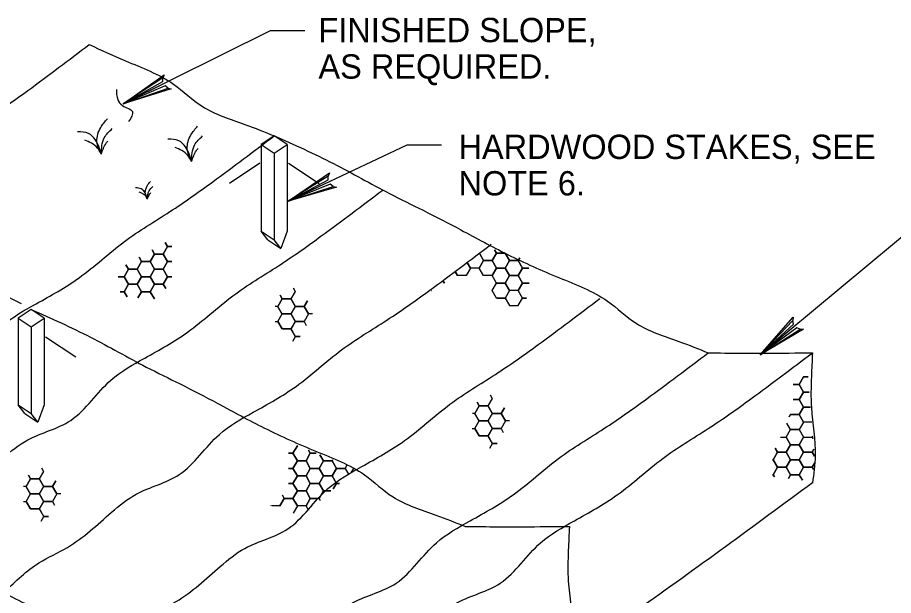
# Model space of a CAD drawing. Extents: x 3 to 3592, y -602 to 1171.
# Drawn here: x 412.5 to 538.6, y 841.3 to 924.6 of the extents above; entities that cross this region are included whole.
import ezdxf

# ---------------------------------------------------------------- set-up
doc = ezdxf.new("R2010")
doc.units = 0
doc.layers.add('2', color=7, linetype='Continuous')
doc.layers.add('3', color=7, linetype='Continuous')

msp = doc.modelspace()

# ---------------------------------------------------------------- linework, layer by layer
at = {"layer": '2'}
for p, q in [((449.46, 907.53), (449.46, 907.53)), ((449.46, 907.53), (449.46, 907.53)), ((449.46, 907.53), (449.46, 907.53)), ((449.46, 907.53), (449.46, 907.53)), ((449.46, 907.53), (449.46, 907.53)), ((449.46, 907.53), (449.46, 907.53)), ((447.58, 906.28), (447.58, 893.78)), ((451.33, 906.28), (451.33, 893.78)), ((451.33, 906.28), (451.33, 906.28)), ((449.46, 905.03), (449.46, 892.53)), ((447.39, 903.59), (443.01, 900.68)), ((451.33, 903.59), (451.33, 903.59)), ((451.53, 903.59), (455.9, 900.68)), ((457.27, 903.63), (457.27, 903.63)), ((447.58, 893.78), (449.46, 892.53)), ((448.52, 892.53), (447.58, 893.78)), ((451.33, 893.78), (450.39, 891.28)), ((448.52, 892.53), (450.39, 891.28)), ((450.39, 891.28), (449.46, 892.53)), ((480.71, 891.91), (480.71, 891.91)), ((413.05, 883.31), (404.04, 887.82)), ((496.33, 884.09), (496.33, 884.09)), ((414.46, 882.53), (414.46, 882.53)), ((414.46, 882.53), (414.46, 882.53)), ((414.46, 882.53), (414.46, 882.53)), ((414.46, 882.53), (414.46, 882.53)), ((414.46, 882.53), (414.46, 882.53)), ((414.46, 882.53), (414.46, 882.53)), ((412.58, 881.28), (412.58, 868.78)), ((416.33, 881.28), (416.33, 868.78)), ((416.33, 881.28), (416.33, 881.28)), ((414.46, 880.03), (414.46, 867.53)), ((416.33, 878.59), (416.33, 878.59)), ((416.53, 878.59), (420.9, 875.68)), ((422.27, 878.63), (422.27, 878.63)), ((511.96, 876.28), (511.96, 876.28)), ((412.58, 868.78), (414.46, 867.53)), ((413.52, 867.53), (412.58, 868.78)), ((416.33, 868.78), (415.39, 866.28)), ((413.52, 867.53), (415.39, 866.28)), ((415.39, 866.28), (414.46, 867.53))]:
    msp.add_line(p, q, dxfattribs=at)
for points in [[(453.87, 922.65), (448.87, 922.65), (427.7, 912.12)], [(434.18, 914.39), (433.73, 914.72), (427.7, 912.12), (434.18, 914.39), (434.62, 914.28), (427.7, 912.12), (433.42, 915.33), (433.42, 915.87), (427.7, 912.12), (433.6, 916.33), (433.42, 915.87)], [(473.56, 906.19), (468.56, 906.19), (451.44, 898.1)], [(457.96, 900.23), (457.52, 900.57), (451.44, 898.1), (457.96, 900.23), (458.4, 900.11), (451.44, 898.1), (457.22, 901.19), (457.23, 901.73), (451.44, 898.1), (457.42, 902.18), (457.23, 901.73)], [(547.75, 895.4), (542.75, 895.4), (519.42, 875.97)], [(433.76, 892.15), (434.09, 891.57)], [(434.09, 891.57), (433.76, 892.15)], [(431.87, 891.09), (432.22, 890.49)], [(432.22, 890.49), (431.87, 891.09)], [(434.09, 891.57), (433.47, 890.49)], [(433.47, 890.49), (434.09, 891.57), (434.7, 891.57)], [(434.7, 891.57), (434.09, 891.57)], [(481.45, 890.65), (480.83, 889.57)], [(480.83, 889.57), (481.45, 890.65)], [(481.19, 891.1), (481.45, 890.65)], [(481.45, 890.65), (481.19, 891.1)], [(481.45, 890.65), (482.61, 890.65)], [(482.61, 890.65), (481.45, 890.65)], [(482.72, 890.62), (483.33, 889.57)], [(483.33, 889.57), (482.72, 890.62)], [(430.34, 889.41), (429.72, 888.33)], [(430.34, 889.41), (429.99, 890.03)], [(429.99, 890.03), (430.34, 889.41)], [(431.59, 889.41), (430.34, 889.41)], [(432.22, 890.49), (431.59, 889.41)], [(433.47, 890.49), (432.22, 890.49)], [(434.7, 889.41), (434.09, 889.41), (433.47, 890.49)], [(433.47, 888.33), (434.09, 889.41), (434.7, 889.41)], [(479.58, 889.57), (478.95, 888.49)], [(479.04, 890.51), (479.58, 889.57)], [(479.58, 889.57), (479.04, 890.51)], [(480.83, 889.57), (479.58, 889.57)], [(481.45, 888.49), (480.83, 889.57)], [(483.33, 889.57), (482.7, 888.49)], [(484.58, 889.57), (483.33, 889.57)], [(484.8, 889.97), (484.58, 889.57)], [(484.58, 889.57), (484.8, 889.97)], [(485.2, 888.49), (484.58, 889.57)], [(428.47, 888.33), (427.84, 887.24)], [(428.47, 888.33), (428.1, 888.96)], [(428.1, 888.96), (428.47, 888.33)], [(429.72, 888.33), (428.47, 888.33)], [(434.7, 887.24), (434.09, 887.24), (433.47, 888.33)], [(477.7, 888.49), (477.08, 887.41)], [(477.7, 888.49), (477.29, 889.2)], [(477.29, 889.2), (477.7, 888.49)], [(478.95, 888.49), (477.7, 888.49)], [(482.7, 888.49), (481.45, 888.49)], [(484.58, 887.41), (485.2, 888.49)], [(485.2, 888.49), (486.12, 888.49)], [(486.12, 888.49), (485.2, 888.49)], [(427.84, 887.24), (426.96, 887.24)], [(426.96, 887.24), (427.84, 887.24)], [(427.84, 887.24), (428.47, 886.16)], [(433.47, 886.16), (434.09, 887.24), (434.7, 887.24)], [(475.83, 887.41), (475.55, 887.89)], [(475.55, 887.89), (475.83, 887.41)], [(477.08, 887.41), (475.83, 887.41)], [(485.2, 886.32), (484.58, 887.41)], [(428.47, 886.16), (427.84, 885.08)], [(427.84, 885.08), (428.47, 886.16)], [(428.47, 886.16), (429.72, 886.16)], [(429.72, 886.16), (430.34, 885.08)], [(431.59, 885.08), (432.22, 886.16)], [(432.22, 886.16), (433.47, 886.16)], [(433.83, 885.53), (433.47, 886.16)], [(433.47, 886.16), (433.83, 885.53)], [(452.19, 885.64), (452.48, 885.13)], [(473.95, 886.32), (473.8, 886.58)], [(473.8, 886.58), (473.95, 886.32)], [(484.58, 885.24), (485.2, 886.32)], [(485.2, 886.32), (486.14, 886.32)], [(486.14, 886.32), (485.2, 886.32)], [(427.84, 885.08), (427.26, 885.08)], [(427.26, 885.08), (427.84, 885.08)], [(428.28, 884.32), (427.84, 885.08)], [(427.84, 885.08), (428.28, 884.32)], [(430.34, 885.08), (429.83, 884.19)], [(429.83, 884.19), (430.34, 885.08)], [(430.34, 885.08), (431.59, 885.08)], [(432.2, 884.03), (431.59, 885.08)], [(431.59, 885.08), (432.2, 884.03)], [(450.31, 884.56), (450.61, 884.04)], [(450.61, 884.04), (450.31, 884.56)], [(452.48, 885.13), (451.86, 884.04)], [(451.88, 884.03), (452.16, 884.52)], [(472.08, 885.24), (472.06, 885.27)], [(472.06, 885.27), (472.08, 885.24)], [(485.2, 884.16), (484.58, 885.24)], [(450.61, 884.04), (449.98, 882.96)], [(451.86, 884.04), (450.61, 884.04)], [(452.5, 882.95), (451.88, 884.03)], [(454.22, 883.77), (453.75, 882.95)], [(453.75, 882.95), (454.22, 883.77)], [(481.45, 884.16), (482.7, 884.16)], [(482.7, 884.16), (483.33, 883.08)], [(483.33, 883.08), (484.58, 883.08)], [(484.58, 883.08), (485.2, 884.16)], [(484.58, 883.08), (484.61, 883.02)], [(484.61, 883.02), (484.58, 883.08)], [(485.2, 884.16), (485.77, 884.16)], [(485.77, 884.16), (485.2, 884.16)], [(449.98, 882.96), (449.61, 882.96)], [(449.98, 880.8), (450.61, 881.88)], [(450.61, 881.88), (451.86, 881.88)], [(451.86, 881.88), (452.48, 880.8)], [(451.88, 881.87), (452.5, 882.95)], [(452.5, 880.78), (451.88, 881.87)], [(453.75, 882.95), (452.5, 882.95)], [(452.5, 882.95), (453.75, 882.95)], [(454.38, 881.87), (453.75, 882.95)], [(453.75, 882.95), (454.38, 881.87)], [(454.38, 881.87), (453.75, 880.78)], [(454.95, 881.87), (454.38, 881.87)], [(449.58, 880.8), (449.98, 880.8)], [(449.98, 880.8), (450.61, 879.72)], [(450.61, 879.72), (449.98, 880.8)], [(452.48, 880.8), (451.86, 879.71)], [(451.88, 879.7), (452.5, 880.78)], [(452.5, 880.78), (453.75, 880.78)], [(453.75, 880.78), (452.5, 880.78)], [(453.75, 880.78), (454.07, 880.23)], [(525.2, 879.68), (524.69, 879.89), (519.42, 875.97), (525.2, 879.68), (525.66, 879.67), (519.42, 875.97), (524.25, 880.42), (524.12, 880.94), (519.42, 875.97), (524.2, 881.43), (524.12, 880.94)], [(450.62, 879.71), (451.86, 879.71)], [(451.86, 879.71), (450.62, 879.71)], [(451.86, 879.71), (452.14, 879.23)], [(452.5, 878.62), (451.88, 879.7)], [(452.11, 877.95), (452.5, 878.62)], [(453.2, 878.62), (452.5, 878.62)], [(452.5, 878.62), (453.2, 878.62)], [(525.05, 871.71), (524.18, 871.71)], [(524.18, 871.71), (525.05, 871.71)], [(525.68, 872.8), (525.05, 871.71)], [(525.05, 871.71), (525.68, 872.8)], [(525.68, 870.63), (525.05, 871.71)], [(525.05, 871.71), (525.68, 870.63)], [(525.62, 872.89), (525.68, 872.8)], [(525.68, 872.8), (525.62, 872.89)], [(525.68, 872.8), (526.32, 872.8)], [(526.32, 872.8), (525.68, 872.8)], [(525.68, 870.63), (525.05, 869.55)], [(525.05, 869.55), (525.68, 870.63)], [(526.5, 870.63), (525.68, 870.63)], [(525.68, 870.63), (526.5, 870.63)], [(478.67, 869.16), (478.97, 868.64)], [(478.97, 868.64), (478.67, 869.16)], [(480.85, 869.72), (480.22, 868.64)], [(480.24, 868.62), (480.53, 869.12)], [(480.55, 870.23), (480.85, 869.72)], [(524.18, 869.55), (525.05, 869.55), (525.68, 868.47), (525.05, 867.38), (523.8, 867.38), (523.77, 867.44)], [(525.05, 869.55), (524.18, 869.55)], [(525.68, 868.47), (525.05, 869.55)], [(478.97, 868.64), (478.35, 867.55)], [(480.22, 868.64), (478.97, 868.64)], [(480.87, 867.54), (480.24, 868.62)], [(482.59, 868.36), (482.12, 867.54)], [(482.12, 867.54), (482.59, 868.36)], [(525.05, 867.38), (525.68, 868.47)], [(526.68, 868.47), (525.68, 868.47)], [(525.68, 868.47), (526.68, 868.47)], [(478.35, 867.55), (477.98, 867.55)], [(480.24, 866.46), (480.87, 867.54)], [(482.12, 867.54), (480.87, 867.54)], [(480.87, 867.54), (482.12, 867.54)], [(482.74, 866.46), (482.12, 867.54)], [(482.12, 867.54), (482.74, 866.46)], [(523.61, 867.04), (523.8, 867.38), (525.05, 867.38), (525.68, 866.3), (525.05, 865.22), (523.8, 865.22), (523.26, 866.17)], [(523.77, 867.44), (523.8, 867.38), (523.61, 867.04)], [(525.68, 866.3), (525.05, 867.38)], [(477.94, 865.39), (478.35, 865.39)], [(478.35, 865.39), (478.97, 866.47)], [(478.35, 865.39), (478.97, 864.31)], [(478.97, 864.31), (478.35, 865.39)], [(478.97, 866.47), (480.22, 866.47)], [(480.22, 866.47), (480.85, 865.39)], [(480.85, 865.39), (480.22, 864.31)], [(480.87, 865.37), (480.24, 866.46)], [(480.24, 864.29), (480.87, 865.37)], [(480.87, 865.37), (482.12, 865.37)], [(482.12, 865.37), (480.87, 865.37)], [(482.74, 866.46), (482.12, 865.37)], [(482.12, 865.37), (482.43, 864.82)], [(483.32, 866.46), (482.74, 866.46)], [(526.86, 866.3), (525.68, 866.3)], [(478.98, 864.31), (480.22, 864.31)], [(480.22, 864.31), (478.98, 864.31)], [(480.22, 864.31), (480.5, 863.82)], [(480.87, 863.21), (480.24, 864.29)], [(522.36, 864.14), (523.18, 864.14), (523.8, 863.05), (523.18, 861.97), (521.93, 861.97), (521.58, 862.57)], [(525.05, 863.05), (525.68, 864.14)], [(525.68, 864.14), (526.93, 864.14)], [(526.93, 864.14), (527.02, 864.3)], [(526.93, 864.14), (527.05, 863.92)], [(527.05, 863.92), (526.93, 864.14)], [(452.78, 862.89), (452.15, 861.81)], [(452.15, 861.81), (452.78, 862.89)], [(452.76, 862.92), (452.78, 862.89)], [(452.78, 862.89), (452.83, 862.89)], [(480.48, 862.54), (480.87, 863.21)], [(481.56, 863.21), (480.87, 863.21)], [(480.87, 863.21), (481.56, 863.21)], [(525.68, 861.97), (525.05, 863.05)], [(451.51, 861.81), (452.15, 861.81), (452.78, 860.72), (452.15, 859.64), (451.51, 859.64)], [(452.15, 861.81), (451.51, 861.81)], [(452.78, 860.72), (452.15, 861.81)], [(454.65, 861.81), (454.03, 860.72)], [(454.03, 860.72), (454.65, 861.81)], [(454.39, 862.26), (454.65, 861.81)], [(454.65, 861.81), (454.39, 862.26)], [(454.65, 861.81), (455.51, 861.81)], [(455.51, 861.81), (454.65, 861.81)], [(456.02, 861.6), (456.53, 860.72)], [(456.53, 860.72), (456.02, 861.6)], [(521.58, 862.57), (521.93, 861.97), (521.3, 860.89), (521.2, 860.89)], [(525.05, 860.89), (525.68, 861.97)], [(525.68, 861.97), (526.93, 861.97)], [(526.93, 861.97), (525.68, 861.97)], [(527.18, 862.4), (526.93, 861.97)], [(526.93, 861.97), (527.18, 862.4)], [(526.93, 861.97), (527.26, 861.4)], [(527.26, 861.4), (526.93, 861.97)], [(454.03, 860.72), (452.78, 860.72)], [(454.65, 859.64), (454.03, 860.72)], [(456.53, 860.72), (455.9, 859.64)], [(455.9, 859.64), (456.53, 860.72)], [(456.53, 860.72), (457.78, 860.72)], [(457.78, 860.72), (456.53, 860.72)], [(457.85, 860.86), (457.78, 860.72)], [(457.78, 860.72), (457.85, 860.86)], [(457.78, 860.72), (458.4, 859.64)], [(458.4, 859.64), (457.78, 860.72)], [(521.2, 860.89), (521.3, 860.89), (521.93, 859.81), (521.3, 858.72), (521.2, 858.72)], [(525.68, 859.81), (525.05, 860.89)], [(527.3, 860.45), (526.93, 859.81)], [(526.93, 859.81), (527.3, 860.45)], [(416.24, 859.21), (415.61, 858.13)], [(415.94, 859.72), (416.24, 859.21)], [(451.51, 859.64), (452.15, 859.64), (452.78, 858.56), (452.15, 857.48), (451.51, 857.48)], [(455.9, 859.64), (454.65, 859.64)], [(456.53, 858.56), (455.9, 859.64)], [(458.4, 859.64), (457.78, 858.56)], [(457.78, 858.56), (458.4, 859.64)], [(458.4, 859.64), (459.65, 859.64)], [(459.65, 859.64), (458.4, 859.64)], [(459.88, 860.04), (459.65, 859.64)], [(459.65, 859.64), (460.2, 858.69)], [(460.52, 858.98), (460.9, 859.63)], [(521.3, 858.72), (521.93, 859.81)], [(521.93, 859.81), (523.18, 859.81)], [(523.18, 859.81), (523.8, 858.72)], [(525.05, 858.72), (525.68, 859.81)], [(526.93, 859.81), (525.68, 859.81)], [(525.68, 859.81), (526.93, 859.81)], [(527.12, 859.47), (526.93, 859.81)], [(526.93, 859.81), (527.12, 859.47)], [(414.36, 858.13), (413.74, 857.05)], [(414.06, 858.65), (414.36, 858.13)], [(414.36, 858.13), (414.06, 858.65)], [(415.61, 858.13), (414.36, 858.13)], [(415.63, 858.12), (415.92, 858.61)], [(416.26, 857.03), (415.63, 858.12)], [(417.98, 857.85), (417.51, 857.03)], [(417.51, 857.03), (417.98, 857.85)], [(455.9, 857.48), (456.53, 858.56)], [(456.53, 858.56), (457.78, 858.56)], [(457.78, 858.56), (456.53, 858.56)], [(457.78, 858.56), (458.4, 857.48)], [(458.4, 857.48), (457.78, 858.56)], [(521.2, 858.72), (521.3, 858.72)], [(521.49, 858.41), (521.3, 858.72)], [(521.3, 858.72), (521.49, 858.41)], [(523.8, 858.72), (523.49, 858.17)], [(523.49, 858.17), (523.8, 858.72)], [(523.8, 858.72), (525.05, 858.72)], [(525.51, 857.93), (525.05, 858.72)], [(525.05, 858.72), (525.51, 857.93)], [(413.74, 857.05), (413.37, 857.05)], [(415.63, 855.95), (416.26, 857.03)], [(417.51, 857.03), (416.26, 857.03)], [(416.26, 857.03), (417.51, 857.03)], [(418.13, 855.95), (417.51, 857.03)], [(417.51, 857.03), (418.13, 855.95)], [(451.51, 857.48), (452.15, 857.48), (452.78, 856.39), (452.15, 855.31), (450.9, 855.31), (450.64, 855.76)], [(454.03, 856.39), (454.65, 857.48)], [(454.65, 857.48), (455.9, 857.48)], [(455.9, 857.48), (456.53, 856.39)], [(456.53, 856.39), (455.9, 857.48)], [(458.4, 857.48), (457.95, 856.69)], [(457.95, 856.69), (458.4, 857.48)], [(458.4, 857.48), (458.83, 857.48)], [(458.83, 857.48), (458.4, 857.48)], [(413.74, 854.88), (414.36, 855.97)], [(414.36, 855.97), (415.61, 855.97)], [(415.61, 855.97), (416.24, 854.88)], [(416.26, 854.87), (415.63, 855.95)], [(418.13, 855.95), (417.51, 854.87)], [(418.71, 855.95), (418.13, 855.95)], [(450.9, 855.31), (450.28, 854.23)], [(450.28, 854.23), (450.9, 855.31)], [(450.64, 855.76), (450.9, 855.31)], [(450.9, 855.31), (452.15, 855.31)], [(452.15, 855.31), (452.78, 854.23)], [(454.65, 855.31), (454.03, 856.39)], [(454.03, 854.23), (454.65, 855.31)], [(455.9, 855.31), (454.65, 855.31)], [(454.65, 855.31), (455.9, 855.31)], [(456.53, 856.39), (455.9, 855.31)], [(455.9, 855.31), (456.53, 856.39)], [(456.07, 855.02), (455.9, 855.31)], [(455.9, 855.31), (456.07, 855.02)], [(456.53, 856.39), (457.61, 856.39)], [(457.61, 856.39), (456.53, 856.39)], [(413.33, 854.88), (413.74, 854.88)], [(413.74, 854.88), (414.36, 853.8)], [(414.36, 853.8), (413.74, 854.88)], [(416.24, 854.88), (415.61, 853.8)], [(415.63, 853.79), (416.26, 854.87)], [(416.26, 854.87), (417.51, 854.87)], [(417.51, 854.87), (416.26, 854.87)], [(417.51, 854.87), (417.82, 854.32)], [(449.02, 854.23), (449, 854.27)], [(449, 854.27), (449.02, 854.23)], [(450.28, 854.23), (449.09, 854.23)], [(450.33, 854.13), (450.28, 854.23)], [(452.78, 854.23), (452.17, 853.18)], [(454.42, 853.55), (454.03, 854.23)], [(414.37, 853.8), (415.61, 853.8)], [(415.61, 853.8), (414.37, 853.8)], [(415.61, 853.8), (415.89, 853.32)], [(416.26, 852.7), (415.63, 853.79)], [(415.87, 852.04), (416.26, 852.7)], [(416.95, 852.7), (416.26, 852.7)], [(416.26, 852.7), (416.95, 852.7)]]:
    msp.add_lwpolyline(points, dxfattribs=at)
for points in [[(449.46, 907.53), (447.58, 906.28), (449.46, 905.03), (451.33, 906.28)], [(429.72, 888.33), (430.34, 889.41), (431.59, 889.41), (432.22, 888.33), (431.59, 887.24), (430.34, 887.24)], [(431.59, 889.41), (432.22, 890.49), (433.47, 890.49), (434.09, 889.41), (433.47, 888.33), (432.22, 888.33)], [(478.95, 888.49), (479.58, 889.57), (480.83, 889.57), (481.45, 888.49), (480.83, 887.41), (479.58, 887.41)], [(482.7, 888.49), (483.33, 889.57), (484.58, 889.57), (485.2, 888.49), (484.58, 887.41), (483.33, 887.41)], [(427.84, 887.24), (428.47, 888.33), (429.72, 888.33), (430.34, 887.24), (429.72, 886.16), (428.47, 886.16)], [(431.59, 887.24), (432.22, 888.33), (433.47, 888.33), (434.09, 887.24), (433.47, 886.16), (432.22, 886.16)], [(480.83, 887.41), (481.45, 888.49), (482.7, 888.49), (483.33, 887.41), (482.7, 886.32), (481.45, 886.32)], [(429.72, 886.16), (430.34, 887.24), (431.59, 887.24), (432.22, 886.16), (431.59, 885.08), (430.34, 885.08)], [(482.7, 886.32), (483.33, 887.41), (484.58, 887.41), (485.2, 886.32), (484.58, 885.24), (483.33, 885.24)], [(480.83, 885.24), (481.45, 886.32), (482.7, 886.32), (483.33, 885.24), (482.7, 884.16), (481.45, 884.16)], [(449.98, 882.96), (450.61, 884.04), (451.86, 884.04), (452.48, 882.96), (451.86, 881.88), (450.61, 881.88)], [(414.46, 882.53), (412.58, 881.28), (414.46, 880.03), (416.33, 881.28)], [(478.35, 867.55), (478.97, 868.64), (480.22, 868.64), (480.85, 867.55), (480.22, 866.47), (478.97, 866.47)], [(523.18, 864.14), (523.8, 865.22), (525.05, 865.22), (525.68, 864.14), (525.05, 863.05), (523.8, 863.05)], [(523.18, 861.97), (523.8, 863.05), (525.05, 863.05), (525.68, 861.97), (525.05, 860.89), (523.8, 860.89)], [(521.3, 860.89), (521.93, 861.97), (523.18, 861.97), (523.8, 860.89), (523.18, 859.81), (521.93, 859.81)], [(452.15, 859.64), (452.78, 860.72), (454.03, 860.72), (454.65, 859.64), (454.03, 858.56), (452.78, 858.56)], [(523.18, 859.81), (523.8, 860.89), (525.05, 860.89), (525.68, 859.81), (525.05, 858.72), (523.8, 858.72)], [(454.03, 858.56), (454.65, 859.64), (455.9, 859.64), (456.53, 858.56), (455.9, 857.48), (454.65, 857.48)], [(413.74, 857.05), (414.36, 858.13), (415.61, 858.13), (416.24, 857.05), (415.61, 855.97), (414.36, 855.97)], [(452.15, 857.48), (452.78, 858.56), (454.03, 858.56), (454.65, 857.48), (454.03, 856.39), (452.78, 856.39)], [(452.15, 855.31), (452.78, 856.39), (454.03, 856.39), (454.65, 855.31), (454.03, 854.23), (452.78, 854.23)]]:
    msp.add_lwpolyline(points, close=True, dxfattribs=at)
for points in [[(352.82, 870.67), (357.68, 874.78), (361.8, 877.02), (368.16, 882.07), (371.71, 884.69), (377.88, 887.49), (380.87, 890.3), (383.67, 893.29), (388.54, 896.47), (394.71, 900.21), (401.25, 905.45), (407.8, 909.75), (413.97, 914.05), (422.82, 920.67)], [(422.82, 920.67), (428.02, 918.33), (434.94, 914.96), (439.06, 911.78), (445.23, 909.16), (449.46, 907.53)], [(426.73, 914.18), (426.91, 912.77), (427.61, 911.89), (429.02, 911.01), (428.49, 909.6)], [(424.55, 904.88), (423.93, 906.72), (424.46, 908.73), (425.42, 909.96)], [(424.55, 904.88), (424.98, 907.25), (426.12, 908.56)], [(437.55, 903.83), (436.93, 905.66), (437.46, 907.68), (438.42, 908.9)], [(379.46, 857.53), (384.32, 861.65), (388.43, 863.89), (394.79, 868.94), (398.34, 871.56), (404.51, 874.36), (407.5, 877.17), (410.31, 880.16), (415.17, 883.34), (421.34, 887.08), (427.89, 892.31), (434.43, 896.61), (440.6, 900.91), (449.46, 907.53)], [(424.55, 904.88), (423.67, 906.98), (422.71, 907.86), (421.13, 908.12)], [(437.55, 903.83), (436.67, 905.93), (435.71, 906.8), (434.13, 907.06)], [(437.55, 903.83), (437.98, 906.19), (439.12, 907.5)], [(449.46, 907.53), (457.99, 903.53), (466.03, 899.23), (470.89, 896.8), (476.31, 893.99), (483.05, 890.44), (490.52, 887.08), (497.44, 883.71), (501.56, 880.53), (507.73, 877.91), (511.96, 876.28)], [(424.55, 904.88), (424.02, 905.76), (423.15, 906.46), (422.18, 906.9)], [(424.55, 904.88), (425.25, 906.46), (425.51, 906.81)], [(437.55, 903.83), (437.02, 904.7), (436.14, 905.4), (435.18, 905.84)], [(437.55, 903.83), (438.25, 905.4), (438.51, 905.75)], [(431.2, 898.4), (430.89, 899.32), (431.16, 900.33), (431.64, 900.94)], [(395.08, 849.72), (399.94, 853.83), (404.06, 856.08), (410.41, 861.13), (413.97, 863.74), (420.14, 866.55), (423.13, 869.35), (425.93, 872.34), (430.8, 875.52), (436.97, 879.26), (443.51, 884.5), (450.05, 888.8), (456.23, 893.1), (465.08, 899.72)], [(431.2, 898.4), (430.76, 899.45), (430.28, 899.89), (429.49, 900.02)], [(431.2, 898.4), (430.94, 898.84), (430.5, 899.19), (430.02, 899.41)], [(431.2, 898.4), (431.42, 899.59), (431.99, 900.24)], [(431.2, 898.4), (431.55, 899.19), (431.68, 899.37)], [(410.71, 841.91), (415.57, 846.02), (419.68, 848.26), (426.04, 853.31), (429.59, 855.93), (435.76, 858.74), (438.75, 861.54), (441.56, 864.53), (446.42, 867.71), (452.59, 871.45), (459.14, 876.69), (465.68, 880.99), (471.85, 885.29), (480.71, 891.91)], [(426.33, 834.09), (431.19, 838.21), (435.31, 840.45), (441.66, 845.5), (445.22, 848.12), (451.39, 850.92), (454.38, 853.73), (457.18, 856.72), (462.05, 859.9), (468.22, 863.64), (474.76, 868.87), (481.3, 873.17), (487.48, 877.47), (496.33, 884.09)], [(414.46, 882.53), (422.99, 878.53), (431.03, 874.23), (435.89, 871.8), (441.31, 868.99), (448.05, 865.44), (455.52, 862.08), (462.44, 858.71), (466.56, 855.53), (472.73, 852.91), (476.96, 851.28)], [(441.96, 826.28), (446.82, 830.4), (450.93, 832.64), (457.29, 837.69), (460.84, 840.31), (467.01, 843.11), (470, 845.92), (472.81, 848.91), (477.67, 852.09), (483.84, 855.83), (490.39, 861.06), (496.93, 865.36), (503.1, 869.66), (511.96, 876.28)], [(456.96, 826.28), (461.82, 830.4), (465.93, 832.64), (472.29, 837.69), (475.84, 840.31), (482.01, 843.11), (485, 845.92), (487.81, 848.91), (492.67, 852.09), (498.84, 855.83), (505.39, 861.06), (511.93, 865.36), (518.1, 869.66), (526.96, 876.28)], [(511.96, 876.28), (516.7, 876.23), (520.25, 876.23), (526.96, 876.28)], [(526.96, 876.28), (526.8, 872.86), (526.8, 868.38), (527.36, 861.46), (526.96, 857.53)], [(379.46, 857.53), (387.99, 853.53), (396.03, 849.23), (400.89, 846.8), (406.31, 843.99), (413.05, 840.44), (420.52, 837.08), (427.44, 833.71), (431.56, 830.53), (437.73, 827.91), (441.96, 826.28)], [(526.96, 857.56), (501.79, 839.28), (484.92, 827.49), (469.07, 815.99), (456.96, 807.56)], [(441.96, 820.03), (437.42, 823.13), (432, 824.62), (423.95, 829.33), (416.11, 833.04), (411.8, 834.35), (408.33, 837.14), (401.33, 839.58), (397.41, 842.39), (392.7, 844.96), (386.94, 846.69), (382.82, 850.43), (377.08, 852.77)], [(476.96, 851.28), (481.7, 851.23), (485.25, 851.23), (491.96, 851.28)], [(491.96, 851.28), (491.8, 847.86), (491.8, 843.38), (492.36, 836.46), (491.96, 832.53)]]:
    msp.add_spline(points, degree=3, dxfattribs=at)

# ---------------------------------------------------------------- texts
at = {"layer": '3'}
for s, p in [('FINISHED SLOPE,', (455.82, 921.01)), ('AS REQUIRED.', (455.82, 915.76)), ('HARDWOOD STAKES, SEE', (475.99, 904.19)), ('NOTE 6.', (475.99, 898.94))]:
    msp.add_text(s, height=3.5, dxfattribs=at).set_placement(p)

doc.saveas('drawing.dxf')
